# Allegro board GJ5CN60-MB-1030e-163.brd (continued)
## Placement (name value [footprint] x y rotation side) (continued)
R424  -  [M-R0402]  68.15 170.89 0 top
R425  -  [M-R0402]  64.85 170.89 180 top
R426  -  [M-R0402]  72.47 170.01 180 top
R427  -  [M-R0402]  63.07 170.89 0 top
R428  -  [M-R0402]  65.73 170.01 0 top
R429  -  [M-R0402]  70.69 170.01 0 top
R430  -  [M-R0402]  58.5 163.4 180 top
R431  -  [M-R0402]  102.44 23.83 0 top
R432  -  [M-R0402]  117.93 130 180 top
R433  -  [M-R0402]  117.93 132.29 180 top
R434  -  [M-R0402]  95.2 47.2 90 top
R435  -  [M-R0402]  92.91 20.78 90 top
R436  -  [M-R0402]  86.31 76.66 90 top
R437  -  [M-R0402]  97.23 76.66 90 top
R438  -  [M-R0402]  93.55 74.63 90 top
R439  -  [M-R0402]  92.66 74.6 270 top
R440  -  [M-R0402]  96.34 74.63 270 top
R441  -  [M-R0402]  88.47 76.66 90 top
R442  -  [M-R0402]  113.36 12.4 90 top
R443  -  [M-R0402]  95.45 7.57 180 top
R444  -  [M-R0402]  71.14 172.93 90 top
R460  -  [M-R0402]  154.63 12.14 270 top
R463  -  [M-R0402]  72.03 172.93 90 top
R472  -  [M-R0402]  153.36 12.14 270 top
R475  -  [M-R0402]  145.52 53.34 180 bottom
R477  -  [M-R0402]  66.12 172.88 90 top
R482  -  [M-R0402]  151.18 50.14 0 bottom
R483  -  [M-R0402]  145.52 50.68 180 bottom
R484  -  [M-R0402]  109.8 6.05 270 bottom
R485  -  [M-R0402]  108.91 6.05 270 bottom
R486  -  [M-R0402]  149.86 53.6 0 bottom
R487  -  [M-R0402]  126.06 6.56 180 top
R488  -  [M-R0402]  126.19 8.21 180 top
R489  -  [M-R0402]  55.19 158.7 180 top
R492  -  [M-R0402]  145.52 51.57 180 bottom
R493  -  [M-R0402]  56.72 163.4 180 top
R494  -  [M-R0402]  55.07 163.91 270 top
R495  -  [M-R0402]  54.18 163.91 90 top
R496  -  [M-R0402]  67 172.88 90 top
R497  -  [M-R0402]  68.66 172.93 90 top
R498  -  [M-R0402]  69.54 172.93 90 top
R499  -  [M-R0402]  63.58 172.93 90 top
R500  -  [M-R0402]  64.46 172.93 90 top
R501  -  [M-R0402]  151.18 51.92 0 bottom
R502  -  [M-R0402]  71.2 175.72 90 top
R504  -  [M-R0402]  72.08 175.72 90 top
R505  -  [M-R0402]  188.29 152.99 180 top
R506  -  [M-R0603]  62.84 160.28 0 top
R507  -  [M-R0402]  66.12 175.72 90 top
R508  -  [M-R0805]  183.69 77.47 0 bottom
R509  -  [M-R0402]  71.5 164.34 90 top
R510  -  [M-R0603]  186.13 72.04 90 bottom
R511  -  [M-R0402]  190.07 143.34 180 top
R512  -  [M-R0402]  190.07 142.45 0 top
R513  -  [M-R0402]  181.81 154.89 180 top
R514  -  [M-R0402]  190.45 149.81 90 top
R515  -  [M-R0402]  191.34 149.81 270 top
R516  -  [M-R0402]  67 175.72 90 top
R517  -  [M-R0402]  69.54 175.72 90 top
R518  -  [M-R0402]  68.66 175.72 90 top
R519  -  [M-R0402]  64.46 175.72 90 top
R521  -  [M-R0402]  190.07 141.56 0 top
R522  -  [M-R0402]  178.89 147.02 0 top
R523  -  [M-R0402]  178.89 147.91 0 top
R524  -  [M-R0402]  178.89 148.8 0 top
R525  -  [M-R0402]  178.89 149.81 0 top
R526  -  [M-R0402]  178.89 150.96 0 top
R527  -  [M-R0402]  178.89 151.84 0 top
R528  -  [M-R0402]  77.67 155.71 0 bottom
R529  -  [M-R0402]  185.88 139.02 90 top
R530  -  [M-R0402]  186.89 139.02 90 top
R531  -  [M-R0402]  187.91 139.02 90 top
R532  -  [M-R0402]  183.69 154 0 top
R533  -  [M-R0402]  183.69 154.89 0 top
R534  -  [M-R0402]  182.7 140.92 180 top
R535  -  [M-R0402]  182.7 140.03 0 top
R536  -  [M-R0402]  184.1 141.13 90 top
R537  -  [M-R0402]  63.58 175.72 90 top
R538  -  [M-R0402]  184.99 141.18 90 top
R539  -  [M-R0402]  180.54 141.3 90 top
R542  -  [M-R0402]  77.67 154.82 0 bottom
R544  -  [M-R0402]  58.62 175.21 0 top
R547  -  [M-R0402]  181.43 141.3 90 top
R548  -  [M-R0402]  178.38 141.81 90 top
R549  -  [M-R0402]  176.73 141.81 270 top
R550  -  [M-R0402]  178.89 144.1 0 top
R551  -  [M-R0402]  178.89 143.21 0 top
R552  -  [M-R0603]  14.05 84.92 90 top
R553  -  [M-R0402]  178.51 145.49 90 top
R554  -  [M-R0402]  177.62 145.49 270 top
R557  -  [M-R0402]  166.45 13.8 90 bottom
R558  -  [M-R0402]  178.89 154.51 0 top
R559  -  [M-R0402]  178.89 153.62 180 top
R560  -  [M-R0402]  185.88 152.99 180 top
R566  -  [M-R0402]  126.03 158.78 180 top
R567  -  [M-R0402]  134.52 158.93 180 top
R568  -  [M-R0402]  141.63 158.3 180 top
R569  -  [M-R0402]  117.85 158.73 180 top
R570  -  [M-R0402]  152.09 152.99 180 top
R571  -  [M-R0402]  160.98 153.17 180 top
R573  -  [M-R0402]  126.06 157.56 180 top
R574  -  [M-R0402]  133.93 157.58 90 top
R575  -  [M-R0402]  141.65 157.38 180 top
R576  -  [M-R0402]  117.85 157.43 180 top
R577  -  [M-R0402]  151.66 152.12 180 top
R578  -  [M-R0402]  160.96 152.1 180 top
R579  -  [M-R0603]  132.28 153.77 0 top
R580  -  [M-R0603]  139.78 153.55 0 top
R581  -  [M-R0603]  148.11 153.65 0 top
R582  -  [M-R0603]  124.69 153.93 0 top
R583  -  [M-R0603]  159.18 148.67 0 top
R584  -  [M-R0603]  168.6 148.03 90 top
R585  -  [M-R0402]  177.75 164.54 270 top
R586  -  [M-R0402]  19.4 156.29 0 bottom
R599  -  [M-R0402]  128.17 171.02 270 top
R600  -  [M-R0402]  129.06 171.02 270 top
R605  -  [M-R0402]  131.44 171.02 270 top
R606  -  [M-R0402]  130.55 171.02 270 top
R607  -  [M-R0402]  133.6 171 270 top
R608  -  [M-R0402]  132.71 171 270 top
R623  -  [M-R0402]  116.41 168.61 0 top
R624  -  [M-R0402]  82.23 173.06 0 top
R625  -  [M-R0402]  89.6 173.06 0 top
R626  -  [M-R0402]  86.43 173.06 0 top
R627  -  [M-R0402]  84.01 173.06 0 top
R632  -  [M-R0402]  152.65 178.23 90 bottom
R653  -  [M-R0402]  174.7 163.78 270 top
R661  -  [M-R0402]  112.98 5.54 90 bottom
R662  -  [M-R0402]  111.2 5.54 270 bottom
R664  -  [M-R0603]  100.91 4.65 0 bottom
R674  -  [M-R0402]  53.54 170.26 0 top
R687  -  [M-R0402]  122.5 168.99 90 bottom
R688  -  [M-R0402]  117.93 166.96 90 bottom
R691  -  [M-R0402]  192.61 147.15 180 top
R750  -  [M-R0402]  192.61 146.13 180 top
R756  -  [M-R0402]  106.12 84.92 0 top
R764  -  [M-R0402]  105.87 63.45 270 top
R765  -  [M-R0402]  106.12 84.03 0 top
R780  -  [M-R0402]  190.07 145.24 0 top
R785  -  [M-R0402]  192.61 145.24 180 top
R787  -  [M-R0402]  100.53 77.8 0 top
R790  -  [M-R0402]  100.53 76.91 180 top
R791  -  [M-R0402]  100.53 79.58 0 top
R792  -  [M-R0402]  100.53 81.36 0 top
R793  -  [M-R0402]  151.76 178.23 90 bottom
R794  -  [M-R0402]  190.07 148.03 180 top
R795  -  [M-R0402]  13.16 64.09 180 top
R803  -  [M-R0402]  181.81 154 180 top
R812  -  [M-R0402]  1.85 103.58 270 top
R815  -  [M-R0402]  100.53 78.69 180 top
R816  -  [M-R0402]  95.45 76.66 90 top
R817  -  [M-R0402]  95.45 74.63 90 top
R818  -  [M-R0402]  100.53 76.15 0 top
R819  -  [M-R0402]  100.53 80.47 180 top
R820  -  [M-R0402]  97.74 72.34 0 top
R821  -  [M-R0402]  99.14 76.66 90 top
R822  -  [M-R0402]  98.12 74.63 270 top
R823  -  [M-R0402]  100.53 74.25 0 top
R824  -  [M-R0402]  98.12 76.66 90 top
R825  -  [M-R0402]  97.74 71.45 180 top
R828  -  [M-R0402]  93.04 61.17 180 top
R832  -  [M-R0402]  95.07 59.64 0 top
R834  -  [M-R0402]  93.04 60.28 0 top
R835  -  [M-R0402]  3.89 104.22 270 top
R836  -  [M-R0402]  9.47 106.89 90 top
R837  -  [M-R0603]  10.36 97.74 270 top
R838  -  [M-R0603]  10.49 101.04 180 top
R842  -  [M-R0603]  183.64 103.94 90 top
R845  -  [M-R0402]  92.53 76.66 90 top
R849  -  [M-R0402]  82.63 57.86 0 top
R850  -  [M-R0402]  4.01 113.62 180 top
R854  -  [M-R0402]  187.55 105.24 0 top
R860  -  [M-R0402]  97.74 73.23 0 top
R861  -  [M-R0402]  97.23 74.63 270 top
R867  -  [M-R0402]  2.11 113.62 180 top
R869  -  [M-R0402]  6.96 107.52 180 top
R879  -  [M-R0402]  176.61 11.26 90 top
R880  -  [M-R0402]  190.19 8.46 0 top
R881  -  [M-R0402]  178.76 17.86 180 top
R882  -  [M-R0402]  153.49 9.73 90 top
R883  -  [M-R0402]  154.51 9.73 90 top
R884  -  [M-R0402]  150.44 11.64 90 top
R885  -  [M-R0402]  151.46 11.64 90 top
R886  -  [M-R0402]  188.16 8.46 0 top
R887  -  [M-R0402]  73.86 121.62 180 bottom
R888  -  [M-R0402]  83.13 121.49 0 bottom
R889  -  [M-R0402]  175.98 15.35 180 top
R890  -  [M-R0402]  63.7 141.56 270 bottom
R892  -  [M-R0402]  54.81 103.97 0 bottom
R893  -  [M-R0402]  94.06 140.41 180 bottom
R894  -  [M-R0402]  63.7 136.1 270 bottom
R895  -  [M-R0402]  94.06 138.13 180 bottom
R896  -  [M-R0402]  53.67 68.28 180 top
R897  -  [M-R0402]  47.7 69.29 270 top
R898  -  [M-R0402]  35.89 106.76 0 bottom
R899  -  [M-R0402]  47.95 65.74 90 top
R900  -  [M-R0402]  47.7 67.52 90 top
R901  -  [M-R0402]  53.67 69.42 0 top
R902  -  [M-R0402]  94.44 29.04 90 top
R903  -  [M-R0402]  38.56 106.76 0 bottom
R904  -  [M-R0402]  62.81 142.07 270 bottom
R905  -  [M-R0402]  79.7 54.44 0 top
R906  -  [M-R0402]  62.05 137.11 270 bottom
R907  -  [M-R0402]  55.96 115.52 0 bottom
R909  -  [M-R0805]  100.91 6.56 0 bottom
R911  -  [M-R0402]  60.91 162 90 top
R912  -  [M-R0402]  68.22 161.75 270 top
R913  -  [M-R0402]  56.01 86.44 0 bottom
R914  -  [M-R0402]  53.8 101.17 0 top
R915  -  [M-R0402]  37.41 72.34 180 bottom
R916  -  [M-R0402]  37.41 104.6 180 bottom
R917  -  [M-R0402]  39.19 72.34 180 bottom
R918  -  [M-R0603]  23.95 74.37 270 bottom
R919  -  [M-R0402]  39.19 104.6 180 bottom
R920  -  [M-R0402]  76.4 77.04 0 top
R921  -  [M-R0402]  66.37 75.39 90 top
R922  -  [M-R0402]  24.21 68.15 180 bottom
R923  -  [M-R0402]  26.11 68.53 180 bottom
R924  -  [M-R0402]  92.66 43.51 0 top
R925  -  [M-R0603]  22.55 74.37 270 bottom
R926  -  [M-R0402]  17.98 102.44 0 top
R927  -  [M-R0402]  12.27 72.6 0 top
R928  -  [M-R0402]  19.18 66.3 90 bottom
R930  -  [M-R0402]  20.27 66.3 90 bottom
R931  -  [M-R0402]  90.25 46.31 90 top
R933  -  [M-R0402]  13.41 112.22 90 top
R934  -  [M-R0805]  89.61 67.77 180 top
R935  -  [M-R0402]  17.09 111.08 90 top
R936  -  [M-R0402]  17.09 109.05 90 top
R937  -  [M-R0402]  102.06 162.77 90 top
R938  -  [M-R0402]  26.11 67.67 180 bottom
R939  -  [M-R0402]  24.21 70.03 0 bottom
R940  -  [M-R0402]  106.37 8.33 90 top
R941  -  [M-R0402]  104.98 161.37 90 top
R942  -  [M-R0402]  63.88 62.56 270 bottom
R943  -  [M-R0402]  14.3 116.41 0 top
R944  -  [M-R0402]  26.57 70.01 270 bottom
R945  -  [M-R0402]  14.3 115.52 180 top
R946  -  [M-R0402]  99.74 111.64 270 top
R947  -  [M-R0402]  16.33 68.28 0 bottom
R948  -  [M-R0402]  14.68 107.27 270 top
R949  -  [M-R0402]  24.21 69.04 180 bottom
R950  -  [M-R0402]  22.81 119.33 0 top
R951  -  [M-R0402]  190.07 147.15 0 top
R952  -  [M-R0402]  21.64 108.79 180 top
R953  -  [M-R0402]  190.07 146.13 0 top
R954  -  [M-R0402]  19.38 72.09 270 top
R955  -  [M-R0402]  24.43 111.08 90 top
R956  -  [M-R0402]  25.68 70.01 270 bottom
R957  -  [M-R0402]  24.08 108.66 180 top
R958  -  [M-R0402]  16.33 71.83 180 bottom
R959  -  [M-R0402]  13.92 70.56 270 bottom
R960  -  [M-R0402]  22.05 67.64 0 bottom
R961  -  [M-R0402]  16.2 73.74 0 bottom
R962  -  [M-R0402]  22.1 66.78 180 bottom
R963  -  [M-R0402]  76.53 47.7 90 top
R964  -  [M-R0402]  25.98 71.83 0 bottom
R965  -  [M-R0402]  23.72 66.73 270 bottom
R966  -  [M-R0402]  77.67 55.32 90 top
R967  -  [M-R0402]  18.49 67.64 180 bottom
R968  -  [M-R0402]  16.2 67.39 180 bottom
R969  -  [M-R0402]  16.2 74.63 0 bottom
R970  -  [M-R0603]  21.06 120.48 90 top
R971  -  [M-R0402]  18.87 111.08 90 top
R972  -  [M-R0402]  23.32 115.9 180 top
R973  -  [M-R0402]  16.33 73.61 0 top
R974  -  [M-R0402]  14.3 112.22 90 top
R975  -  [M-R0402]  15.19 112.22 90 top
R976  -  [M-R0402]  15.7 110.7 180 top
R977  -  [M-R0402]  73.99 47.7 270 top
R978  -  [M-R0402]  73.61 51.39 270 top
R979  -  [M-R0402]  23.32 114.89 180 top
R980  -  [M-R0402]  12.14 81.11 180 top
R981  -  [M-R0402]  23.32 131.14 180 top
R982  -  [M-R0402]  23.44 146.51 180 top
R983  -  [M-R0402]  23.32 158.58 180 top
R984  -  [M-R0402]  23.32 114 180 top
R985  -  [M-R0402]  23.29 113.13 180 top
R986  -  [M-R0402]  68.32 159.85 90 top
R987  -  [M-R0402]  19.38 108.79 270 top
R988  -  [M-R0402]  14.17 72.72 0 bottom
R989  -  [M-R0402]  79.83 157.31 90 bottom
R990  -  [M-R0402]  25.22 114 180 top
R991  -  [M-R0402]  25.22 114.89 180 top
R992  -  [M-R0402]  22.68 111.08 90 top
R993  -  [M-R0402]  18.24 70.69 90 top
R994  -  [M-R0402]  21.79 111.08 90 top
R995  -  [M-R0402]  25.22 112.8 180 top
R996  -  [M-R0402]  20.9 111.08 90 top
R997  -  [M-R0402]  16.33 70.06 180 bottom
R998  -  [M-R0402]  14.68 109.05 90 top
R999  -  [M-R0402]  16.33 70.95 180 bottom
R1000  -  [M-R0402]  107.26 8.33 90 top
R1001  -  [M-R0805]  79.2 61.8 90 top
R1002  -  [M-R0402]  20.22 108.82 270 top
R1007  -  [M-R0402]  79.83 48.59 270 top
R1010  -  [M-R0402]  181.28 74.93 270 bottom
R1014  -  [M-R0402]  183.64 68.33 0 bottom
R1022  -  [M-R0402]  68.4 155.4 90 bottom
R1054  -  [M-R0603]  21.03 147.4 90 top
R1060  -  [M-R0402]  19.13 131.4 180 top
R1061  -  [M-R0402]  19.76 137.62 180 top
R1064  -  [M-R0603]  21.03 149.94 180 top
R1065  -  [M-R0603]  20.27 122.51 180 top
R1066  -  [M-R0402]  23.19 150.07 0 top
R1083  VALUE  [TOPSHORT-R0201]  11.38 59.26 270 bottom
R1084  VALUE  [TOPSHORT-R0201]  3.89 117.05 0 top
R1085  VALUE  [TOPSHORT-R0201]  5.66 59.13 270 top
R1091  VALUE  [TOPSHORT-R0201]  10.62 59.26 270 bottom
R1092  VALUE  [TOPSHORT-R0201]  3.89 117.94 0 top
R1093  VALUE  [TOPSHORT-R0201]  5.03 59.13 270 top
R1125  -  [M-R0402]  4.77 108.41 180 top
R1126  -  [M-R0402]  5.13 109.86 90 top
R1397  -  [M-R0402]  84.91 45.8 0 top
R1398  -  [M-R0402]  95.96 161.12 0 top
R1794  -  [M-R0402]  24.08 107.01 90 top
R1795  -  [M-R0402]  11.76 105.11 180 top
R1907  -  [M-R0402]  89.99 51.39 0 top
R1908  -  [M-R0402]  94.82 45.67 180 top
R1912  -  [M-R0402]  98.5 53.42 180 top
R1920  -  [M-R0402]  95.33 44.28 270 top
R1921  -  [M-R0402]  93.55 44.66 0 top
R1925  -  [M-R0402]  98.5 51.51 180 top
R1929  -  [M-R0402]  21.28 102.44 0 top
R1932  -  [M-R0402]  14.3 113.74 0 top
R1934  -  [M-R0603]  12.65 99.39 270 top
R1936  -  [M-R0402]  94.18 47.2 270 top
R2665  -  [M-R0402]  169.62 12.91 90 top
R2667  -  [M-R0402]  173.94 9.6 270 top
R2685  -  [M-R0402]  79.2 138.76 180 bottom
R2686  -  [M-R0402]  81.48 139.02 0 bottom
R2691  -  [M-R0402]  78.31 140.16 90 top
R2692  -  [M-R0402]  79.32 140.16 270 top
R2693  -  [M-R0402]  80.21 140.16 90 top
R2712  -  [M-R0402]  35.51 122.25 0 top
R2713  -  [M-R0402]  38.43 122 0 top
R2714  -  [M-R0402]  36.14 87.46 0 top
R2715  -  [M-R0402]  37.03 120.73 180 bottom
R2716  -  [M-R0402]  36.91 121.87 270 top
R2717  -  [M-R0402]  38.05 87.46 0 top
R2718  -  [M-R0402]  38.43 84.28 0 bottom
R2719  -  [M-R0402]  36.14 88.34 180 top
R2729  -  [M-R0402]  96.97 109.71 0 bottom
R2731  -  [M-R0402]  46.3 138.89 0 bottom
R2732  -  [M-R0402]  37.03 90 180 bottom
R2733  -  [M-R0402]  79.2 135.97 180 bottom
R2734  -  [M-R0402]  81.48 136.35 0 bottom
R2735  -  [M-R0402]  79.2 136.86 180 bottom
R2736  -  [M-R0402]  81.48 137.24 0 bottom
R2737  -  [M-R0402]  40.97 122.13 270 bottom
R2738  -  [M-R0402]  40.08 122.13 270 bottom
R2739  -  [M-R0402]  46.3 136.22 0 bottom
R2740  -  [M-R0402]  46.3 137.11 0 bottom
R2741  -  [M-R0402]  40.99 87.18 270 bottom
R2742  -  [M-R0402]  40 87.18 270 bottom
R2745  -  [M-R0402]  39.95 89.49 90 bottom
R2746  -  [M-R0402]  40.84 89.49 90 bottom
R2751  -  [M-R0402]  2.36 108.41 0 top
R2755  -  [M-R0402]  4.24 109.83 270 top
R2758  -  [M-R0402]  69.92 109.43 270 bottom
R2759  -  [M-R0402]  68.27 121.87 90 bottom
R2760  -  [M-R0402]  69.16 121.87 90 bottom
R2771  -  [M-R0402]  95.71 84.79 270 bottom
R2773  -  [M-R0402]  2.36 109.3 180 top
R2781  -  [M-R0402]  94.51 76.66 270 top
R2798  -  [M-R0402]  98.5 59.95 270 top
R2799  -  [M-R0402]  102.44 94.57 0 top
R2800  -  [M-R0402]  102.44 93.68 0 top
R2801  -  [M-R0402]  93.55 76.66 270 top
R2803  -  [M-R0402]  87.45 76.66 90 top
R2806  -  [M-R0402]  91.01 84.66 90 bottom
R2808  -  [M-R0402]  91.67 74.6 270 top
R2809  -  [M-R0402]  90.5 74.63 270 top
R2810  -  [M-R0402]  94.56 74.63 90 top
R2811  -  [M-R0402]  90.5 76.66 90 top
R2812  -  [M-R0402]  88.34 74.76 90 top
R2813  -  [M-R0402]  89.61 74.63 270 top
R2814  -  [M-R0402]  96.34 76.66 90 top
R2815  -  [M-R0402]  91.64 76.66 90 top
R2836  -  [M-R0402]  89.36 76.66 270 top
R2848  -  [M-R0402]  92.4 70.95 180 top
R2849  -  [M-R0402]  92.4 71.83 180 top
R2850  -  [M-R0402]  93.8 67.01 90 top
R2865  -  [M-R0402]  103.58 72.98 0 top
R2875  -  [M-R0402]  100.53 73.36 180 top
R2876  -  [M-R0402]  100.53 72.47 0 top
R2877  -  [M-R0402]  105.23 82.12 180 top
R2878  -  [M-R0402]  91.77 86.06 0 bottom
R2879  -  [M-R0402]  20.65 72.09 270 top
R2880  -  [M-R0402]  16.33 119.21 180 top
R2881  -  [M-R0402]  105.36 72.98 0 top
R2921  -  [M-R0402]  94.82 70.95 0 top
R2924  -  [M-R0402]  92.4 72.72 180 top
R2925  -  [M-R0402]  92.28 67.01 90 top
R2938  -  [M-R0402]  87.58 72.47 270 top
R2939  -  [M-R0402]  100.15 112.98 0 top
R2940  -  [M-R0402]  20.65 106.89 270 top
R2941  -  [M-R0402]  13.03 70.56 90 bottom
R2942  -  [M-R0402]  21.67 106.89 270 top
R2949  -  [M-R0402]  87.45 74.76 270 top
R3036  -  [M-R0402]  72.85 162.39 270 top
R3129  -  [M-R0402]  167.97 130 180 top
R3197  -  [M-R0402]  192.35 119.59 180 top
R3198  -  [M-R0402]  190.45 116.28 180 top
R3201  -  [M-R0402]  187.53 104.35 0 top
R3202  -  [M-R0402]  188.72 102.92 270 top
R3204  -  [M-R0402]  108.53 73.49 90 top
R3240  -  [M-R0402]  103.2 5.92 90 bottom
R3247  -  [M-R0402]  93.04 7.57 180 top
R3290  -  [M-R0402]  156.41 25.23 0 top
R3295  -  [M-R0402]  63.58 37.67 270 top
R3298  -  [M-R0402]  62.69 37.67 270 top
R3299  -  [M-R0402]  72.34 40.08 0 top
R3305  -  [M-R0402]  69.54 37.67 90 top
R3306  -  [M-R0402]  66.24 37.67 90 top
R3307  -  [M-R0402]  61.42 45.93 180 top
R3308  -  [M-R0402]  68.66 37.67 270 top
R3309  -  [M-R0402]  72.47 41.23 180 top
R3310  -  [M-R0402]  69.93 44.28 0 top
R3311  -  [M-R1206]  19.38 42.62 0 top
R3312  -  [M-R0603]  50.62 56.98 180 top
R3313  -  [M-R0402]  44.02 39.58 90 bottom
R3314  -  [M-R0402]  37.79 41.48 270 bottom
R3315  -  [M-R0402]  39.95 41.48 270 bottom
R3316  -  [M-R0402]  40.59 36.78 90 top
R3318  -  [M-R0402]  63.58 45.93 180 top
R3319  -  [M-R0402]  65.35 37.67 90 top
R3320  -  [M-R0402]  69.93 42.24 0 top
R3321  -  [M-R0603]  67.39 35.26 90 top
R3322  -  [M-R0402]  64.46 37.67 90 top
R3323  -  [M-R0402]  72.47 43.39 180 top
R3324  -  [M-R0402]  43.13 41.48 270 bottom
R3325  -  [M-R0402]  73.48 35.26 90 top
R3326  -  [M-R0402]  45.92 156.67 0 bottom
R3327  -  [M-R0402]  64.97 46.18 90 top
R3328  -  [M-R0402]  60.15 44.53 270 top
R3329  -  [M-R0402]  59.26 44.53 90 top
R3330  -  [M-R0402]  60.65 41.48 180 top
R3331  -  [M-R0402]  61.67 38.81 90 top
R3332  -  [M-R0402]  69.04 46.31 90 top
R3333  -  [M-R0402]  28.9 38.05 270 top
R3334  -  [M-R0402]  69.93 43.39 180 top
R3335  -  [M-R0402]  68.15 46.31 90 top
R3336  -  [M-R0402]  65.86 46.18 90 top
R3361  -  [M-R0402]  91.52 42.57 180 top
R3365  -  [M-R0402]  84.66 47.32 90 top
R3366  -  [M-R0402]  97.13 162.77 90 top
R3367  -  [M-R0402]  84.66 49.23 90 top
R3368  -  [M-R0402]  87.32 49.23 270 top
R3369  -  [M-R0402]  98.86 163.27 180 top
R3370  -  [M-R0402]  103.83 162.77 270 top
R3372  -  [M-R0402]  111.33 124.62 0 bottom
R3375  -  [M-R0402]  95.33 162.77 270 top
R3376  -  [M-R0402]  111.33 126.65 0 bottom
R3377  -  [M-R0402]  111.33 127.54 0 bottom
R3379  -  [M-R0402]  102.77 159.13 180 top
R3381  -  [M-R0402]  187.91 98.38 180 top
R3382  -  [M-R0402]  193.8 96.22 180 top
R3385  -  [M-R0402]  86.44 47.32 270 top
R3395  -  [M-R0402]  85.55 49.23 270 top
R3402  -  [M-R0402]  86.44 49.23 270 top
R3494  -  [M-R0402]  101.17 162.77 90 top
R3512  -  [M-R0402]  167.33 11 270 top
R3514  -  [M-R0402]  166.45 11 270 top
R3515  -  [M-R0402]  146.25 5.67 90 bottom
R3516  -  [M-R0603]  100.91 3.25 0 bottom
R3517  -  [M-R0402]  143.84 5.54 270 bottom
R3518  -  [M-R0402]  159.21 3.76 90 bottom
R3519  -  [M-R0603]  100.91 1.86 0 bottom
R3520  -  [M-R0402]  154.76 4.91 270 bottom
R3521  -  [M-R0402]  105.49 8.33 90 top
R3523  -  [M-R0402]  107.14 6.05 90 bottom
R3536  -  [M-R0402]  82.63 59.77 0 top
R3537  -  [M-R0402]  9.85 105.11 180 top
R3539  -  [M-R0402]  102.74 60.12 90 top
R3540  -  [M-R0402]  95.07 58.75 0 top
R3541  -  [M-R0402]  16.15 109.05 90 top
R3585  -  [M-R0402]  165.05 8.59 270 top
R3624  -  [M-R0402]  17.63 156.29 180 bottom
R3625  -  [M-R0402]  29.16 161.5 180 top
R3626  -  [M-R0402]  11.1 70.56 270 bottom
R3627  -  [M-R0402]  18.24 58.37 90 bottom
R3628  -  [M-R0402]  17.22 58.37 90 bottom
R3654  -  [M-R0402]  117.93 168.74 90 bottom
R3692  -  [M-R0402]  91.52 155.53 0 bottom
R3693  -  [M-R0402]  86.82 157.94 90 bottom
R3694  -  [M-R0402]  112.47 170.77 270 top
R3695  -  [M-R0402]  111.45 170.77 270 top
R3697  -  [M-R0402]  114.45 170.77 270 top
R3698  -  [M-R0402]  113.54 170.77 270 top
R3699  -  [M-R0402]  109.04 170.77 270 top
R3700  -  [M-R0402]  110.06 170.77 270 top
R3702  -  [M-R0402]  166.45 8.59 90 top
R3710  -  [M-R0402]  11.76 47.07 0 bottom
R3711  -  [M-R0402]  11.76 47.96 0 bottom
R3716  -  [M-R0402]  104.6 8.33 270 top
R3721  -  [M-R0402]  11.68 61.83 0 bottom
R3722  -  [M-R0402]  24.18 71.81 0 bottom
R3723  -  [M-R0402]  174.95 155.02 90 top
R3724  -  [M-R0402]  181.3 165.05 270 top
R3820  -  [M-R0402]  99.77 162.89 180 bottom
R3821  -  [M-R0402]  99.77 162 0 bottom
R3822  -  [M-R0402]  184.76 114.74 270 top
RCH1  -  [M-R1206]  49.61 38.05 90 top
RCH2  -  [M-R1206]  47.19 38.05 90 top
RT10  -  [M-R0603]  143.97 15.19 0 bottom
S1  -  [SCON2S]  28.51 172.05 90 bottom
S4  -  [SCON2S]  164.53 172.3 270 bottom
S5  -  [SCON2S]  79.37 38.63 180 bottom
S6  -  [SCON2S]  80.67 38.63 180 bottom
S7  -  [SCON2S]  76.88 38.61 180 bottom
S8  -  [SCON2S]  78.05 38.63 180 bottom
S10  *  [SCON2S]  64.79 179.53 0 bottom
S11  *  [SCON2S]  63.8 179.53 0 bottom
S12  *  [SCON2S]  69.29 180.04 180 bottom
S13  *  [SCON2S]  68.32 180.04 180 bottom
S14  -  [SCON2S]  69.29 157.81 90 bottom
S15  -  [SCON2S]  74.62 157.56 90 bottom
S16  -  [SCON2S]  75.51 157.56 270 bottom
S17  -  [SCON2S]  184.1 162.39 270 top
S18  *  [SCON2S]  66.09 155.86 90 bottom
S19  *  [SCON2S]  67.79 179.53 0 bottom
S20  *  [SCON2S]  66.8 179.56 0 bottom
S21  *  [SCON2S]  66.24 181.11 0 bottom
S22  *  [SCON2S]  65.35 181.11 0 bottom
S23  *  [SCON2S]  55.19 172.16 180 top
S25  -  [SCON2S]  126.35 176.39 90 bottom
S26  -  [SCON2S]  130.88 174.94 270 bottom
S27  -  [SCON2S]  129.89 176.41 270 bottom
S28  -  [SCON2S]  132.83 174.86 270 bottom
S29  -  [SCON2S]  133.87 176.39 270 bottom
S30  -  [SCON2S]  135.9 176.41 270 bottom
S106  -  [SCON2S]  40.97 48.72 180 top
S107  -  [SCON2S]  42.49 48.72 180 top
S108  -  [SCON2S]  39.45 48.72 180 top
S109  -  [SCON2S]  44.02 48.72 180 top
S110  -  [SCON2S]  15.37 162.92 90 bottom
S111  -  [SCON2S]  181.86 164.37 270 bottom
S112  -  [SCON2S]  109.8 176.48 270 bottom
S113  -  [SCON2S]  115.77 176.33 270 bottom
S114  -  [SCON2S]  112.24 176.56 90 bottom
S115  -  [SCON2S]  106.25 176.48 90 bottom
S116  -  [SCON2S]  111.56 175.67 45 bottom
S117  -  [SCON2S]  110.44 175.72 315 bottom
SW1  Value*  [SWITCH_T-V_SFNQGMP21E8T_FH]  27.4 169.1 0 bottom
SW2  Value*  [SWITCH_T-V_SFNQGMP21E8T_FH]  182.99 161.43 180 bottom
SW3  Value*  [SWITCH_T-V_SFNQGMP21E8T_FH]  14.23 161.43 180 bottom
SW5  -  [M-SOT23-3L]  121.08 172.95 180 bottom
SW6  VALUE  [SWITCH_T_V_ML4L12XQR_DIP]  165.95 170.16 180 bottom
TP1  -  [TP20]  142.37 7.7 270 top
TP2  -  [TP20]  141.05 7.7 0 top
TP3  -  [TP20]  69.16 114.76 180 bottom
TP4  -  [TP20]  9.22 72.85 0 top
TP5  -  [TP20]  3.12 70.31 0 top
TP6  -  [TP20]  3.5 65.48 0 top
TP7  -  [TP20]  149.48 111.54 180 bottom
TP9  -  [TP20]  166.45 130 0 top
TP10  -  [TP20]  122.76 12.02 0 top
TP11  -  [TP20]  166.06 124.67 0 top
TP13  -  [TP20]  119.71 103.84 0 top
TP14  -  [TP20]  147.66 111.46 180 bottom
TP15  -  [TP20]  166.32 128.22 0 top
TP16  -  [TP20]  159.43 125.2 180 bottom
TP18  -  [TP20]  122.25 14.43 180 bottom
TP19  -  [TP20]  130 18.62 180 bottom
TP20  -  [TP20]  99.59 95.99 0 top
TP21  -  [TP20]  101.04 88.85 0 top
TP23  -  [TP20]  99.8 94.49 0 top
TP24  -  [TP20]  123.62 23.14 180 bottom
TP25  -  [TP20]  124.66 20.78 180 bottom
TP26  -  [TP20]  103.58 24.84 0 top
TP27  -  [TP20]  125.17 21.67 180 bottom
TP28  -  [TP20]  122.12 12.27 180 bottom
TP29  -  [TP20]  125.45 10.57 0 top
TP30  -  [TP20]  125.04 14.81 180 bottom
TP31  -  [TP20]  119.4 12.8 0 top
TP32  -  [TP20]  100.86 95.33 0 top
TP33  -  [TP20]  125.42 11.76 0 top
TP34  -  [TP20]  100.84 96.88 0 top
TP35  -  [TP20]  102.36 95.35 0 top
TP36  -  [TP20]  101.09 93.68 0 top
TP37  -  [TP20]  100.66 23.32 0 top
TP38  -  [TP20]  103.58 19.26 0 top
TP39  -  [TP20]  164.54 111.84 0 top
TP41  -  [TP20]  165.94 120.35 0 top
TP42  -  [TP20]  165.94 119.08 0 top
TP43  -  [TP20]  167.46 119.08 0 top
TP44  -  [TP20]  167.46 120.35 0 top
TP45  -  [TP20]  166.06 111.84 0 top
TP46  -  [TP20]  164.41 113.24 0 top
TP47  -  [TP20]  166.83 113.24 0 top
TP48  -  [TP20]  165.43 113.24 0 top
TP50  -  [TP20]  124.66 11.89 180 bottom
TP51  -  [TP20]  103.71 26.5 0 top
TP52  -  [TP20]  131.77 24.21 0 top
TP53  -  [TP20]  101.68 22.43 0 top
TP54  -  [TP20]  103.83 21.92 180 bottom
TP55  -  [TP20]  104.98 23.19 180 bottom
TP95  -  [TP20]  92.68 93.6 180 bottom
TP96  -  [TP20]  91.13 93.55 180 bottom
TP150  -  [TP20]  23.62 65.31 90 top
TP151  -  [TP20]  143.84 10.11 180 bottom
TP152  -  [TP20]  144.22 12.91 180 bottom
TP184  -  [TP20]  83.77 7.7 90 top
TP185  -  [TP20]  90.68 10.01 90 bottom
TP186  -  [TP20]  91.26 11.92 180 bottom
TP187  -  [TP20]  90.17 7.9 90 top
TP190  -  [TP20]  90.02 11.81 180 bottom
TP193  -  [TP20]  88.87 7.72 0 top
TP194  -  [TP20]  88.95 11.51 90 bottom
TP198  -  [TP20]  141.53 31.32 0 bottom
TP199  -  [TP20]  164.57 31.55 180 bottom
TP1903  -  [TP20]  98.96 50.6 270 top
U1  -  [QFN-16_4X4_D65]  6.46 68.56 0 top
U2  -  [SOT-23-5]  56.22 55.59 270 top
U3  VALUE*  [QFN48_D4-6X6]  184.48 146.76 90 top
U4  MP86901-BGLT  [TQFN21_3X4_MP86901B]  129.89 156.82 90 top
U5  -  [QFPS128-04M-60]  155.02 20.91 270 bottom
U6  MP86901-BGLT  [TQFN21_3X4_MP86901B]  137.26 156.34 90 top
U7  -  [QFN48_D4-6X6]  23.32 59.77 270 top
U8  -  [M-SOP8_150MIL]  145.62 23.83 0 top
U9  APW8715QBI-TRG  [TQFN23_0D5_4X4_APW8715AA8]  189.43 94.06 270 top
U10  MP86901-BGLT  [TQFN21_3X4_MP86901B]  145.41 156.67 90 top
U11  MP86901-BGLT  [TQFN21_3X4_MP86901B]  121.66 156.75 90 top
U12  APW8715QBI-TRG  [TQFN23_0D5_4X4_APW8715AA8]  180.3 13.7 0 top
U13  MP86901-BGLT  [TQFN21_3X4_MP86901B]  155.78 151.21 90 top
U14  -  [M-SOP8_150MIL]  22.02 140.64 90 bottom
U15  MP86901-BGLT  [TQFN21_3X4_MP86901B]  164.62 151.23 90 top
U16  -  [M-SOP8_150MIL]  191.34 163.66 0 top
U17  APW8715QBI-TRG  [TQFN23_0D5_4X4_APW8715AA8]  87.58 42.75 270 top
U18  APW8715QBI-TRG  [TQFN23_0D5_4X4_APW8715AA8]  99.26 159.08 270 top
U19  *  [WDFN10-1_0D5_2D0X2D0_3X3]  62.23 61.67 90 top
U20  -  [M-SOP8-208MIL]  135.46 24.46 0 top
U23  -  [M-SOT353]  180.54 136.22 270 top
U24  -  [M-SOT353]  99.77 160.1 90 bottom
U25  VALUE  [QFN16_3X3_NB687]  186.29 108.77 180 top
U26  -  [BGA1440_CFL_H62_5_MA_KOZ]  141.98 117.38 270 top
U27  -  [M-MSOP8]  141.3 169.75 270 top
U28  -  [BGA874_CNP_H_5_MA_KOZ]  117.55 26.37 0 top
U29  -  [M-SOT353]  83.26 155.4 270 bottom
U30  *  [WDFN10-1_0D5_2D0X2D0_3X3]  85.29 57.48 180 top
U31  -  [M-MSOP8]  120.65 169.93 270 top
U32  VAL  [WDFN8_0D5_1D0_2D0X2D0]  22.09 148.35 270 bottom
U83  -  [M-SOP8_150MIL]  104.82 77.55 180 top
U84  *  [WDFN10-1_0D5_2D0X2D0_3X3]  6.93 102.7 180 top
U97  *  [QFN28-1_0D4_2D4X2D4_4X4]  65.1 41.74 0 top
U104  -  [DFN3X2-14L]  172.67 58.5 180 bottom
U105  -  [DFN3X2-14L]  114.58 125.76 90 bottom
U106  -  [DFN3X2-14L]  170.49 15.64 270 bottom
U107  -  [DFN3X2-14L]  75.01 61.55 0 top
U721  -  [QFN20_3X3_D4]  20.01 70.44 270 bottom
U722  -  [QFN4X4-24-0-5]  19 115.78 0 top
U733  -  [M-MSOP8]  105.87 165.43 270 top
U1901  VALUE*  [QFN-32_4X4_0D4]  94.44 51.64 0 top
Y1  -  [CRYSTAL-2P_3D2X1D5_0D9]  137.49 15.83 270 top
Y2  -  [CRYSTAL-4P_3D2X2D5_0D9]  103.2 51.39 270 top
Y3  -  [CRYSTAL-4P_3D2X2D5_0D9]  99.77 29.49 90 bottom
Y10  -  [CRYSTAL-4P_3D2X2D5_0D9]  101.93 84.53 90 top

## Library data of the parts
AB1 AB3-AB5 AR5 AR6 AR8 AR9 AR11-AR14 AR17 AR18 B27 B34 R1 R2 R4 R5 R7-R16 R19-R22 R24-R30 R32 R33 R36-R89 R91-R105 R107 R109-R114 R116-R119 R121-R128 R131-R146 R148 R149 R151 R153 R155-R158 R163-R180 R182-R188 R191-R208 R211 R215-R225 R227 R228 R235 R236 R241 R245-R260 R262 R264 R266 R269 R271 R273 R278 R281 R283-R309 R311-R317 R319-R321 R323 R325-R327 R329 R334-R343 R347-R350 R352-R358 R360-R363 R366-R371 R373 R375 R377-R379 R383-R386 R388 R389 R392-R394 R398 R403-R405 R408 R412-R420 R424-R444 R460 R463 R472 R475 R477 R482-R489 R492-R502 R504 R505 R507 R509 R511-R519 R521-R532 R534-R539 R542 R544 R548-R550 R554 R557-R560 R566-R571 R573-R578 R585 R586 R599 R600 R605-R608 R623-R627 R632 R653 R661 R662 R674 R687 R688 R691 R750 R756 R764 R765 R780 R785 R787 R790-R795 R803 R812 R815-R825 R828 R832 R834-R836 R845 R849 R850 R854 R860 R861 R867 R869 R879-R890 R892-R907 R911-R917 R919-R924 R926-R928 R930 R931 R933 R935-R969 R971-R1000 R1002 R1007 R1010 R1014 R1022 R1060 R1061 R1066 R1125 R1126 R1397 R1398 R1794 R1795 R1907 R1908 R1912 R1920 R1921 R1925 R1929 R1932 R1936 R2665 R2667 R2685 R2686 R2691-R2693 R2712-R2719 R2729 R2731-R2742 R2745 R2746 R2751 R2755 R2758-R2760 R2771 R2773 R2781 R2798-R2801 R2803 R2806 R2808-R2815 R2836 R2848-R2850 R2865 R2875-R2881 R2921 R2924 R2925 R2938-R2942 R2949 R3036 R3129 R3197 R3198 R3201 R3202 R3204 R3240 R3247 R3290 R3295 R3298 R3299 R3305-R3310 R3313-R3316 R3318-R3320 R3322-R3336 R3361 R3365-R3370 R3372 R3375-R3377 R3379 R3381 R3382 R3385 R3395 R3402 R3494 R3512 R3514 R3515 R3517 R3518 R3520 R3521 R3523 R3536 R3537 R3539-R3541 R3585 R3624-R3628 R3654 R3692-R3695 R3697-R3700 R3702 R3710 R3711 R3716 R3721-R3724 R3820-R3822 = M-R0402
AB2 AB6 AR25 B1 R3 R6 R31 R35 R189 R190 R213 R214 R226 R230 R232 R239 R242 R280 R310 R322 R372 R374 R376 R409 R422 R506 R510 R552 R579-R584 R664 R837 R838 R842 R918 R925 R970 R1054 R1064 R1065 R1934 R3312 R3321 R3516 R3519 RT10 = M-R0603
AB8 AB9 AB11 AB12 B7 B10 B12 B19 = M-B0603
AC3 AC5-AC7 AC9 C2 C4 C8 C13-C19 C21 C42 C44-C50 C52-C54 C56-C66 C68 C69 C72-C76 C78 C80 C82-C89 C93 C94 C96 C100 C101 C105 C107 C109 C113-C115 C118-C120 C126 C128-C131 C133 C134 C136-C142 C145 C147 C150 C151 C154-C158 C161-C166 C168 C172 C174 C175 C177-C180 C182 C183 C194 C195 C198 C203 C205 C207 C209 C214 C216 C219 C223-C237 C239-C250 C252-C282 C284-C300 C305 C308-C311 C320-C335 C339 C341 C345-C347 C349 C351-C355 C359-C378 C380-C401 C403-C418 C420-C422 C425-C432 C435 C436 C438 C445 C450 C452 C456 C465 C466 C469 C470 C473 C486 C492 C493 C498-C500 C522 C529 C540 C544-C546 C548 C550 C554 C556 C559 C581 C588 C592 C595 C602 C610 C615 C641 C653 C654 C656 C663 C665-C669 C673 C720 C738 C782-C785 C788 C789 C796-C809 C818 C819 C821-C834 C846-C849 C851-C855 C857-C859 C863 C864 C867 C868 C870 C872 C874-C888 C890 C893 C895 C898 C901 C904-C908 C911-C915 C917-C921 C924-C928 C931-C935 C939-C942 C947 C949 C950 C952 C955-C957 C963 C972 C973 C976-C982 C984-C987 C989-C992 C994-C997 C999 C1000 C1002 C1004-C1017 C1019-C1022 C1024-C1026 C1028 C1031 C1032 C1035 C1037 C1038 C1040-C1044 C1046 C1050 C1053-C1057 C1059-C1061 C1063-C1071 C1074-C1077 C1128 C1137 C1151-C1153 C1164 C1170 C1176 C1179-C1197 C1216-C1227 C1243 C1244 C1246 C1248 C1249 C1252 C1260-C1267 C1274 C1277 C1279 C1281-C1285 C1287 C1289-C1296 C1298-C1303 C1307 C1308 C1310-C1318 C1321-C1326 C1328-C1342 C1347 C1349 C1361 C1362 C1364 C1367 C1368 C1371 C1374 C1375 C1382-C1384 C1386-C1390 C1392-C1413 C1415-C1419 C1421 C1422 C1426 C1427 C1432 C1433 C1442-C1446 C1451 C1452 C1456-C1458 C1476-C1483 C1488-C1499 C1504-C1516 C2549-C2555 C2575 C2578 C2579 C2745-C2747 C2821 C3384 C3399 C3401 C3416-C3420 C3422-C3425 C3445 C3463-C3468 C3470 C3471 C3491 C3493 C3495 C3532 C3535-C3537 C3541 C3543 C3549-C3553 C3556-C3560 C3564 C3565 C3574 C3576 C3579-C3583 C3603 C3604 C3616 C3617 C3620-C3623 C3625-C3627 C3630 C3631 C3634 C3635 C3638 C3641 C3643-C3646 C3650 C3669 C3742 C3743 C3847 C3892 C3893 C3895 C3896 C3901-C3904 C3912 C3913 C3939-C3941 C3988 C3989 C4084 C4092 C4094 C4102 C4103 C4114 C4115 = M-C0402
AC4 AC8 C3 C5-C7 C9-C11 C22-C41 C43 C51 C55 C67 C70 C71 C77 C79 C81 C90-C92 C95 C97-C99 C102-C104 C106 C108 C110-C112 C116 C117 C121-C123 C125 C127 C132 C135 C143 C144 C146 C148 C149 C152 C153 C159 C160 C167 C169-C171 C173 C176 C181 C184-C193 C196 C197 C199-C202 C204 C206 C208 C210-C213 C215 C217 C218 C220-C222 C283 C340 C379 C402 C553 C577-C580 C582-C587 C589-C591 C593 C594 C596-C601 C603-C609 C611-C614 C616-C628 C677 C686-C690 C692-C703 C719 C816 C817 C856 C860-C862 C865 C866 C871 C889 C891 C892 C894 C896 C897 C899 C900 C902 C903 C909 C910 C916 C922 C923 C929 C930 C936-C938 C943-C946 C948 C951 C953 C954 C958-C962 C964-C971 C974 C975 C983 C988 C993 C998 C1001 C1003 C1018 C1023 C1027 C1029 C1030 C1033 C1034 C1036 C1039 C1045 C1047-C1049 C1051 C1052 C1058 C1062 C1072 C1073 C1078 C1138 C1139 C1144 C1161 C1163 C1165 C1167 C1169 C1234-C1237 C1245 C1247 C1250 C1251 C1253-C1259 C1268-C1273 C1275 C1276 C1278 C1280 C1286 C1288 C1297 C1304-C1306 C1309 C1319 C1320 C1327 C1343-C1346 C1348 C1350-C1358 C1363 C1370 C1378 C1385 C1391 C1414 C1423 C1425 C1429 C1431 C1434 C1440 C1441 C1447 C1448 C1450 C1454 C1455 C1463-C1468 C1470-C1472 C2396-C2398 C3421 C3426-C3428 C3431 C3432 C3438-C3441 C3443 C3447 C3496 C3538-C3540 C3544-C3548 C3554 C3561-C3563 C3566-C3573 C3575 C3577 C3578 C3584-C3602 C3605-C3615 C3618 C3619 C3624 C3628 C3629 C3632 C3636 C3637 C3642 C3647-C3649 C3651-C3661 C3744 C3745 C3747 C3898 C3990-C3992 C4085 C4093 = M-C0603
ACN1 = CON_WB-4H125_11255W90-NP_JCTC
B2 B15 B16 = M-B0402
B13 B20 B36 B37 = M-B0805: Tolerance: ***; User Part Number: ***
B14 B25 PS1 = FUSE-0805
B26 R508 R934 R1001 = M-R0805
C419 C423 C424 C433 = M-C0402: signal model: M-C0402_.22U-10-04R-K
C576 C630-C632 C1369 C1372 C1373 C1376 C1377 C1438 C3633 C3897 C3899 C3962 C4078 C4079 C4104-C4110 = M-C0805
C629 = M-C1808
C674 C1420 C1428 C1435 C1437 C1449 C1459 C1469 = M-C7343: User Part Number: ***; Tolerance: ***
C675 C1424 C1436 C1439 C1453 = M-C7343: Tolerance: ***; User Part Number: ***
C4117 C4121 = CAP_EEEFZ1E101P_6D3_L45
C4118-C4120 = CAP_EEEFZ1E101P_6D3_L60
CN1 = CON_S-DDR4-S80_D4ASX-260-80_ARG
CN4 = CON_WB_2H125_W-00-1025_JCTC
CN9 CN14 CNDEG1 = CON_WB_10H08_50208-010_ACES
CN11 = CON_S-DDR4-S40_D4ASX-260-40_ARG
CN12 = CON_FFC_50B05_FP225H050S10M_JXT
CN17 = CON_FFC_10R05_6712K-V10N07L_ENT
CN18 = CON_FFC_6R100_51524-00601_ACES
CN19 CN41 CN42 = CON_FFC_6R05-AFC34-S06FCA_HF
CN23 CN32 = CON_SUSB_3SR_UEA1111-R04012_FOX
CN26 = CON_HDMI-A-R_HAR01-191CN5V_HT
CN30 = CON_WB_13V150_51481-01371_ACES
CN34 = CON_RJ45_WO_130456-781_SANTA
CNDCIN1 = CON_DCIN_WO_2DC3003-002211_SIN
CNDEG2 = CON_WB_6H08_88460-0601_ACES
CNEDP1 = CON_FFC_40R05-51517_ACES
CNFAN1 CNFAN2 = CON_WB_3H125_3800K-F03N_ENT
CNHDD1 = CON_FFC_18B05_51625-01801_ACES
CNKB1 = CON_FFC_40TB05_6718K_Y40N_ENT
CNSSD1 CNSSD2 = CON_M2_M_S67_NXSM0-S67XX_ARG
CNWLAN1 = CON_M2-E-S67_AS0BC21-S48BE_FOX
CON3 = CON_SUSB-CS_UT11123-101W0_FXCN
D1 D3 D4 D10 D16 D28 D41 D51 D52 = M-SOT23
D23 D24 D26 D27 D29 D30 = M-SOD323
D37-D39 D42-D45 D59-D62 = DIODE-AZ5315-02F
ESD1-ESD3 = DFN10_0D5_2D5X1D0
G1 = BGA_2152_P070_375X375
H2 H4 = HOLEC276D118
H3 = GI_H3
H5-H7 H25 = C315D110
H8 = GI_H8
H12 = GI_H12
H13-H15 H18-H20 = HOLEC295D157
H16 = C236D158
H23 = C197D79
H24 = HOLEC197D71
JP1 JP2 = TOPOPEN_20X30
L3 L10 L11 L28 L43 = CHOKE_7D6X6D8_4
L12 L14 L15 L17 = CHOKE-7D3_8D3_5
L13 L20 L21 L35 L50 L53 = CHOKE-7D3_6D8_3
L16 L22-L27 L29 L34 L36-L38 L44 L45 L48 L51 L65-L67 = CHOKE-4P_2X1_2X1_2
L46 L49 L62 = CHOKE-4D1_4D0_2D0
L52 = CHOKE_3X3_1D7
L54 = CHOKE_3X3_1D5
LED1 = LED_19-223-R7G: User Part Number: ***; Tolerance: ***
LED2 LED4 = LED_WHITE_4_RNM_RNM: User Part Number: ***; Tolerance: ***
LT2 = GST5009
M1-M8 = M-MARK1
M41-M46 = BGA_0170_P080_140X120
PJP5 PJP11 PJP13 PJP15 PJP28 PJP34 PJP3210 = TOPSHORT_20X30
PJP9 PJP10 PJP12 PJP14 PJP16-PJP24 = TOPOPEN_20X79
PQ37 PQ40-PQ44 PQ48 PQ49 PQ52 PQ53 = PDFN5X6P_8_DUALMOS
Q1 Q5 Q12 Q19 Q27 Q30 Q37 Q42 Q48-Q50 Q54 Q55 Q57 Q59 Q62-Q64 Q66-Q71 Q78 Q86 Q101 Q105 Q106 Q123-Q126 Q129 Q136 Q137 Q139 Q146-Q148 Q155 Q157-Q163 Q183 Q188 Q190 = M-SOT23G
Q2-Q4 Q16 Q44 Q47 Q58 Q60 Q88 Q92 Q100 Q104 Q109 Q113 Q114 Q116 Q119 Q120 Q122 Q128 Q130 = SOT363
Q8-Q10 = PQFN8-PPS
Q20 Q45 Q53 = M-SOT23A: Tolerance: ***; User Part Number: ***
Q41 Q43 = PDFN-8P_B3X3_D65
Q51 Q182 = M-SOT23A: User Part Number: ***; Tolerance: ***
Q96 = M-SOT353: User Part Number: ***; Tolerance: ***
Q99 Q165 U23 U24 U29 = M-SOT353: Tolerance: ***; User Part Number: ***
R150 R181 R359 R365 R533 R547 R551 R553 = M-R0402: signal model: M-R0402_0-04
R344-R346 R387 R3311 RCH1 RCH2 = M-R1206
R351 R364 R380-R382 R390 = M-R0805: Tolerance: ***; User Part Number: ***
R909 = M-R0805: signal model: SMR0402_33-1-04
R1083-R1085 R1091-R1093 = TOPSHORT-R0201
S1 S4-S8 S10-S23 S25-S30 S106-S117 = SCON2S
SW1-SW3 = SWITCH_T-V_SFNQGMP21E8T_FH
SW5 = M-SOT23-3L: Tolerance: ***; User Part Number: ***
SW6 = SWITCH_T_V_ML4L12XQR_DIP
TP1-TP7 TP9-TP11 TP13-TP16 TP18-TP21 TP23-TP39 TP41-TP48 TP50-TP55 TP95 TP96 TP150-TP152 TP184-TP187 TP190 TP193 TP194 TP198 TP199 TP1903 = TP20
U1 = QFN-16_4X4_D65
U2 = SOT-23-5
U3 U7 = QFN48_D4-6X6
U4 U6 U10 U11 U13 U15 = TQFN21_3X4_MP86901B
U5 = QFPS128-04M-60: User Part Number: ***
U8 U14 U16 U83 = M-SOP8_150MIL
U9 U12 U17 U18 = TQFN23_0D5_4X4_APW8715AA8
U19 U30 U84 = WDFN10-1_0D5_2D0X2D0_3X3
U20 = M-SOP8-208MIL
U25 = QFN16_3X3_NB687
U26 = BGA1440_CFL_H62_5_MA_KOZ
U27 U31 U733 = M-MSOP8: User Part Number: ***
U28 = BGA874_CNP_H_5_MA_KOZ
U32 = WDFN8_0D5_1D0_2D0X2D0
U97 = QFN28-1_0D4_2D4X2D4_4X4
U104-U107 = DFN3X2-14L
U721 = QFN20_3X3_D4
U722 = QFN4X4-24-0-5
U1901 = QFN-32_4X4_0D4
Y1 = CRYSTAL-2P_3D2X1D5_0D9
Y2 Y3 Y10 = CRYSTAL-4P_3D2X2D5_0D9

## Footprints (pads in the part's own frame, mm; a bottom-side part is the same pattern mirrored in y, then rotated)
BGA874_CNP_H_5_MA_KOZ
  round 0.305 smd: A2(-11.46,11.314) A3(-10.959,11.314) A4(-10.459,11.314) A46(10.459,11.314) A47(10.959,11.314) A48(11.46,11.314) AA19(-3.099,1.549) AA20(-2.324,1.549) AA22(-1.549,1.549) AA23(-0.775,1.549) AA25(0,1.549) AA27(0.775,1.549) AA28(1.549,1.549) AA30(2.324,1.549) AA31(3.099,1.549) AB19(-3.099,0.775) AB20(-2.324,0.775) AB22(-1.549,0.775) AB23(-0.775,0.775) AB25(0,0.775) AB27(0.775,0.775) AB28(1.549,0.775) AB30(2.324,0.775) AB31(3.099,0.775) AC6(-9.374,0.579) AC7(-8.612,0.579) AC9(-7.85,0.579) AC11(-7.088,0.579) AC12(-6.326,0.579) AC14(-5.564,0.579) AC15(-4.802,0.579) AC17(-4.04,0.579) AC33(4.04,0.579) AC35(4.802,0.579) AC36(5.564,0.579) AC38(6.326,0.579) AC39(7.088,0.579) AC41(7.85,0.579) AC43(8.612,0.579) AC44(9.374,0.579) AD19(-3.099,0) AD20(-2.324,0) AD22(-1.549,0) AD23(-0.775,0) AD25(0,0) AD27(0.775,0) AD28(1.549,0) AD30(2.324,0) AD31(3.099,0) AE6(-9.374,-0.579) AE7(-8.612,-0.579) AE9(-7.85,-0.579) AE11(-7.088,-0.579) AE12(-6.326,-0.579) AE14(-5.564,-0.579) AE15(-4.802,-0.579) AE17(-4.04,-0.579) AE33(4.04,-0.579) AE35(4.802,-0.579) AE36(5.564,-0.579) AE38(6.326,-0.579) AE39(7.088,-0.579) AE41(7.85,-0.579) AE43(8.612,-0.579) AE44(9.374,-0.579) AF19(-3.099,-0.775) AF20(-2.324,-0.775) AF22(-1.549,-0.775) AF23(-0.775,-0.775) AF25(0,-0.775) AF27(0.775,-0.775) AF28(1.549,-0.775) AF30(2.324,-0.775) AF31(3.099,-0.775) AG19(-3.099,-1.549) AG20(-2.324,-1.549) AG22(-1.549,-1.549) AG23(-0.775,-1.549) AG25(0,-1.549) AG27(0.775,-1.549) AG28(1.549,-1.549) AG30(2.324,-1.549) AG31(3.099,-1.549) AH9(-7.919,-2.205) AH10(-7.18,-2.014) AH12(-6.402,-2.014) AH14(-5.564,-2.014) AH15(-4.789,-2.014) AH17(-4.027,-2.014) AH33(4.027,-2.014) AH35(4.789,-2.014) AH36(5.564,-2.014) AH38(6.402,-2.014) AH40(7.18,-2.014) AH41(7.919,-2.205) AJ6(-9.397,-2.586) AJ7(-8.658,-2.395) AJ19(-3.099,-2.324) AJ20(-2.324,-2.324) AJ22(-1.549,-2.324) AJ23(-0.775,-2.324) AJ25(0,-2.324) AJ27(0.775,-2.324) AJ28(1.549,-2.324) AJ30(2.324,-2.324) AJ31(3.099,-2.324) AJ43(8.658,-2.395) AJ44(9.397,-2.586) AK19(-3.099,-3.099) AK20(-2.324,-3.099) AK22(-1.549,-3.099) AK23(-0.775,-3.099) AK25(0,-3.099) AK27(0.775,-3.099) AK28(1.549,-3.099) AK30(2.324,-3.099) AK31(3.099,-3.099) AL9(-7.914,-3.495) AL10(-7.181,-3.259) AL12(-6.419,-3.259) AL13(-5.657,-3.259) AL15(-4.895,-3.259) AL17(-4.133,-3.259) AL21(-2.014,-3.578) AL24(-0.579,-3.591) AL26(0.579,-3.591) AL29(2.014,-3.578) AL33(4.133,-3.259) AL35(4.895,-3.259) AL37(5.657,-3.259) AL38(6.419,-3.259) AL40(7.181,-3.259) AL41(7.914,-3.495) AM7(-8.635,-3.843) AM18(-3.259,-3.683) AM32(3.259,-3.683) AM43(8.635,-3.843) AN6(-9.295,-4.224) AN10(-7.181,-4.656) AN12(-6.444,-4.351) AN13(-5.682,-4.351) AN15(-4.92,-4.351) AN16(-4.351,-4.394) AN18(-3.259,-4.394) AN21(-2.014,-4.289) AN24(-0.579,-4.302) AN26(0.579,-4.302) AN29(2.014,-4.289) AN32(3.259,-4.394) AN34(4.351,-4.394) AN35(4.92,-4.351) AN37(5.682,-4.351) AN38(6.444,-4.351) AN40(7.181,-4.656) AN44(9.295,-4.224) AP9(-7.914,-4.968) AP21(-2.014,-5.064) AP24(-0.579,-5.064) AP26(0.579,-5.064) AP29(2.014,-5.064) AP41(7.914,-4.968) AR8(-8.508,-5.469) AR12(-6.444,-5.443) AR13(-5.682,-5.443) AR15(-4.92,-5.443) AR16(-4.351,-5.182) AR18(-3.259,-5.156) AR32(3.259,-5.156) AR34(4.351,-5.182) AR35(4.92,-5.443) AR37(5.682,-5.443) AR38(6.444,-5.443) AR42(8.508,-5.469) AT6(-9.295,-5.659) AT10(-7.181,-5.773) AT16(-4.351,-5.944) AT18(-3.259,-5.918) AT21(-2.014,-5.902) AT24(-0.579,-5.826) AT26(0.579,-5.826) AT29(2.014,-5.902) AT32(3.259,-5.918) AT34(4.351,-5.944) AT40(7.181,-5.773) AT44(9.295,-5.659) AU9(-7.914,-6.416) AU24(-0.579,-6.588) AU26(0.579,-6.588) AU41(7.914,-6.416) AV6(-9.295,-7.094) AV7(-8.597,-6.764) AV11(-7.079,-6.975) AV13(-5.748,-6.757) AV16(-4.656,-6.719) AV18(-3.259,-6.68) AV21(-2.014,-6.679) AV29(2.014,-6.679) AV32(3.259,-6.68) AV34(4.656,-6.719) AV37(5.748,-6.757) AV39(7.079,-6.975) AV43(8.597,-6.764) AV44(9.295,-7.094) AW9(-7.824,-7.577) AW10(-7.262,-7.509) AW13(-6.01,-7.49) AW15(-4.892,-7.452) AW18(-3.495,-7.413) AW21(-2.205,-7.419) AW24(-0.579,-7.35) AW26(0.579,-7.35) AW29(2.205,-7.419) AW32(3.495,-7.413) AW35(4.892,-7.452) AW37(6.01,-7.49) AW40(7.262,-7.509) AW41(7.824,-7.577) AY8(-8.533,-7.898) AY42(8.533,-7.898) B1(-11.814,10.96) B2(-11.33,10.83) B3(-10.709,10.878) B47(10.709,10.878) B48(11.33,10.83) B49(11.814,10.96) BA6(-9.13,-8.203) BA12(-6.485,-8.135) BA14(-5.24,-8.135) BA17(-3.843,-8.135) BA20(-2.395,-8.158) BA24(-0.579,-8.112) BA26(0.579,-8.112) BA30(2.395,-8.158) BA33(3.843,-8.135) BA36(5.24,-8.135) BA38(6.485,-8.135) BA44(9.13,-8.203) BB6(-9.088,-8.706) BB7(-8.589,-9) BB9(-8.024,-8.774) BB11(-6.866,-8.795) BB14(-5.621,-8.795) BB16(-4.224,-8.795) BB20(-2.586,-8.897) BB24(-0.579,-8.874) BB26(0.579,-8.874) BB30(2.586,-8.897) BB34(4.224,-8.795) BB36(5.621,-8.795) BB39(6.866,-8.795) BB41(8.024,-8.774) BB43(8.589,-9) BB44(9.088,-8.706) BC5(-9.634,-9.254) BC45(9.634,-9.254) BD1(-11.814,-9.959) BD4(-10.474,-9.983) BD46(10.474,-9.983) BD49(11.814,-9.959) BE1(-11.814,-10.459) BE2(-11.373,-10.196) BE3(-10.86,-10.311) BE4(-10.391,-10.487) BE5(-9.965,-10.212) BE45(9.965,-10.212) BE46(10.391,-10.487) BE47(10.86,-10.311) BE48(11.373,-10.196) BE49(11.814,-10.459) BF1(-11.814,-10.96) BF2(-11.33,-10.83) BF3(-10.709,-10.878) BF47(10.709,-10.878) BF48(11.33,-10.83) BF49(11.814,-10.96) BG2(-11.46,-11.314) BG3(-10.959,-11.314) BG4(-10.459,-11.314) BG46(10.459,-11.314) BG47(10.959,-11.314) BG48(11.46,-11.314) C1(-11.814,10.459) C2(-11.373,10.196) C3(-10.86,10.311) C4(-10.391,10.487) C5(-9.965,10.212) C45(9.965,10.212) C46(10.391,10.487) C47(10.86,10.311) C48(11.373,10.196) C49(11.814,10.459) D1(-11.814,9.959) D4(-10.474,9.983) D46(10.474,9.983) D49(11.814,9.959) E5(-9.634,9.254) E45(9.634,9.254) F6(-9.088,8.706) F7(-8.589,9) F9(-8.024,8.774) F11(-6.866,8.795) F14(-5.621,8.795) F16(-4.224,8.795) F20(-2.586,8.897) F24(-0.579,8.874) F26(0.579,8.874) F30(2.586,8.897) F34(4.224,8.795) F36(5.621,8.795) F39(6.866,8.795) F41(8.024,8.774) F43(8.589,9) F44(9.088,8.706) G6(-9.13,8.203) G12(-6.485,8.135) G14(-5.24,8.135) G17(-3.843,8.135) G20(-2.395,8.158) G24(-0.579,8.112) G26(0.579,8.112) G30(2.395,8.158) G33(3.843,8.135) G36(5.24,8.135) G38(6.485,8.135) G44(9.13,8.203) H8(-8.533,7.898) H42(8.533,7.898) J9(-7.824,7.577) J10(-7.262,7.509) J13(-6.01,7.49) J15(-4.892,7.452) J18(-3.495,7.413) J21(-2.205,7.419) J24(-0.579,7.35) J26(0.579,7.35) J29(2.205,7.419) J32(3.495,7.413) J35(4.892,7.452) J37(6.01,7.49) J40(7.262,7.509) J41(7.824,7.577) K6(-9.295,7.094) K7(-8.597,6.764) K11(-7.079,6.975) K13(-5.748,6.757) K16(-4.656,6.719) K18(-3.259,6.68) K21(-2.014,6.679) K29(2.014,6.679) K32(3.259,6.68) K34(4.656,6.719) K37(5.748,6.757) K39(7.079,6.975) K43(8.597,6.764) K44(9.295,7.094) L9(-7.914,6.416) L24(-0.579,6.588) L26(0.579,6.588) L41(7.914,6.416) M6(-9.295,5.659) M10(-7.181,5.773) M16(-4.351,5.944) M18(-3.259,5.918) M21(-2.014,5.902) M24(-0.579,5.826) M26(0.579,5.826) M29(2.014,5.902) M32(3.259,5.918) M34(4.351,5.944) M40(7.181,5.773) M44(9.295,5.659) N8(-8.508,5.469) N12(-6.444,5.443) N13(-5.682,5.443) N15(-4.92,5.443) N16(-4.351,5.182) N18(-3.259,5.156) N32(3.259,5.156) N34(4.351,5.182) N35(4.92,5.443) N37(5.682,5.443) N38(6.444,5.443) N42(8.508,5.469) P9(-7.914,4.968) P21(-2.014,5.064) P24(-0.579,5.064) P26(0.579,5.064) P29(2.014,5.064) P41(7.914,4.968) R6(-9.295,4.224) R10(-7.181,4.656) R12(-6.444,4.351) R13(-5.682,4.351) R15(-4.92,4.351) R16(-4.351,4.394) R18(-3.259,4.394) R21(-2.014,4.289) R24(-0.579,4.302) R26(0.579,4.302) R29(2.014,4.289) R32(3.259,4.394) R34(4.351,4.394) R35(4.92,4.351) R37(5.682,4.351) R38(6.444,4.351) R40(7.181,4.656) R44(9.295,4.224) T7(-8.635,3.843) T17(-3.811,3.683) T18(-3.259,3.683) T32(3.259,3.683) T43(8.635,3.843) U9(-7.914,3.495) U10(-7.181,3.259) U12(-6.419,3.259) U13(-5.657,3.259) U15(-4.895,3.259) U17(-4.133,3.259) U21(-2.014,3.578) U24(-0.579,3.591) U26(0.579,3.591) U29(2.014,3.578) U33(4.133,3.259) U35(4.895,3.259) U37(5.657,3.259) U38(6.419,3.259) U40(7.181,3.259) U41(7.914,3.495) V19(-3.099,3.099) V20(-2.324,3.099) V22(-1.549,3.099) V23(-0.775,3.099) V25(0,3.099) V27(0.775,3.099) V28(1.549,3.099) V30(2.324,3.099) V31(3.099,3.099) W6(-9.397,2.586) W7(-8.658,2.395) W19(-3.099,2.324) W20(-2.324,2.324) W22(-1.549,2.324) W23(-0.775,2.324) W25(0,2.324) W27(0.775,2.324) W28(1.549,2.324) W30(2.324,2.324) W31(3.099,2.324) W43(8.658,2.395) W44(9.397,2.586) Y9(-7.919,2.205) Y10(-7.18,2.014) Y12(-6.402,2.014) Y14(-5.564,2.014) Y15(-4.789,2.014) Y17(-4.027,2.014) Y33(4.027,2.014) Y35(4.789,2.014) Y36(5.564,2.014) Y38(6.402,2.014) Y40(7.18,2.014) Y41(7.919,2.205)
  round 0.279 smd: A5(-9.958,11.314) A45(9.958,11.314) BC1(-11.814,-9.458) BC49(11.814,-9.458) BG5(-9.958,-11.314) BG45(9.958,-11.314) E1(-11.814,9.458) E49(11.814,9.458)
  oval 0.203x0.254 smd: A6(-9.399,11.314) A8(-8.294,11.314) A42(8.294,11.314) A44(9.399,11.314) BD8(-8.411,-9.813) BD12(-6.214,-9.813) BD17(-4.017,-9.813) BD21(-1.82,-9.813) BD29(1.82,-9.813) BD33(4.017,-9.813) BD38(6.214,-9.813) BD42(8.411,-9.813) BE9(-7.784,-10.186) BE10(-7.283,-10.059) BE14(-5.587,-10.186) BE15(-5.086,-10.059) BE18(-3.39,-10.186) BE19(-2.889,-10.059) BE23(-1.193,-10.186) BE24(-0.692,-10.059) BE26(0.692,-10.059) BE27(1.193,-10.186) BE31(2.889,-10.059) BE32(3.39,-10.186) BE35(5.086,-10.059) BE36(5.587,-10.186) BE40(7.283,-10.059) BE41(7.784,-10.186) BG6(-9.399,-11.314) BG8(-8.294,-11.314) BG42(8.294,-11.314) BG44(9.399,-11.314) C9(-7.784,10.186) C10(-7.283,10.059) C14(-5.587,10.186) C15(-5.086,10.059) C18(-3.39,10.186) C19(-2.889,10.059) C23(-1.193,10.186) C24(-0.692,10.059) C26(0.692,10.059) C27(1.193,10.186) C31(2.889,10.059) C32(3.39,10.186) C35(5.086,10.059) C36(5.587,10.186) C40(7.283,10.059) C41(7.784,10.186) D8(-8.411,9.813) D12(-6.214,9.813) D17(-4.017,9.813) D21(-1.82,9.813) D29(1.82,9.813) D33(4.017,9.813) D38(6.214,9.813) D42(8.411,9.813)
  oval 0.152x0.254 smd: A13(-6.072,11.314) A17(-3.875,11.314) A22(-1.678,11.314) A25(0,11.314) A28(1.678,11.314) A33(3.875,11.314) A37(6.072,11.314) B10(-7.123,10.603) B12(-6.265,10.816) B14(-5.587,10.687) B15(-4.926,10.603) B17(-4.068,10.816) B18(-3.39,10.687) B19(-2.729,10.603) B21(-1.871,10.816) B23(-1.193,10.687) B24(-0.532,10.603) B25(0,10.806) B26(0.532,10.603) B27(1.193,10.687) B29(1.871,10.816) B31(2.729,10.603) B32(3.39,10.687) B33(4.068,10.816) B35(4.926,10.603) B36(5.587,10.687) B38(6.265,10.816) B40(7.123,10.603) BE11(-6.76,-10.118) BE12(-6.295,-10.313) BE16(-4.563,-10.118) BE17(-4.098,-10.313) BE20(-2.366,-10.118) BE21(-1.901,-10.313) BE25(0,-10.298) BE29(1.901,-10.313) BE30(2.366,-10.118) BE33(4.098,-10.313) BE34(4.563,-10.118) BE38(6.295,-10.313) BE39(6.76,-10.118) BF10(-7.123,-10.603) BF12(-6.265,-10.816) BF14(-5.587,-10.687) BF15(-4.926,-10.603) BF17(-4.068,-10.816) BF18(-3.39,-10.687) BF19(-2.729,-10.603) BF21(-1.871,-10.816) BF23(-1.193,-10.687) BF24(-0.532,-10.603) BF25(0,-10.806) BF26(0.532,-10.603) BF27(1.193,-10.687) BF29(1.871,-10.816) BF31(2.729,-10.603) BF32(3.39,-10.687) BF33(4.068,-10.816) BF35(4.926,-10.603) BF36(5.587,-10.687) BF38(6.265,-10.816) BF40(7.123,-10.603) BG13(-6.072,-11.314) BG17(-3.875,-11.314) BG22(-1.678,-11.314) BG25(0,-11.314) BG28(1.678,-11.314) BG33(3.875,-11.314) BG37(6.072,-11.314) C11(-6.76,10.118) C12(-6.295,10.313) C16(-4.563,10.118) C17(-4.098,10.313) C20(-2.366,10.118) C21(-1.901,10.313) C25(0,10.298) C29(1.901,10.313) C30(2.366,10.118) C33(4.098,10.313) C34(4.563,10.118) C38(6.295,10.313) C39(6.76,10.118)
  oval 0.254x0.152 smd: AA1(-11.814,1.678) AA49(11.814,1.678) AB2(-11.187,1.193) AB48(11.187,1.193) AC2(-11.103,0.532) AC48(11.103,0.532) AD1(-11.814,0) AD2(-11.306,0) AD3(-10.798,0) AD47(10.798,0) AD48(11.306,0) AD49(11.814,0) AE2(-11.103,-0.532) AE48(11.103,-0.532) AF2(-11.187,-1.193) AF48(11.187,-1.193) AG1(-11.814,-1.678) AG49(11.814,-1.678) AH2(-11.316,-1.871) AH3(-10.813,-1.901) AH47(10.813,-1.901) AH48(11.316,-1.871) AJ3(-10.618,-2.366) AJ47(10.618,-2.366) AK2(-11.103,-2.729) AK48(11.103,-2.729) AL2(-11.187,-3.39) AL48(11.187,-3.39) AM1(-11.814,-3.875) AM2(-11.316,-4.068) AM3(-10.813,-4.098) AM47(10.813,-4.098) AM48(11.316,-4.068) AM49(11.814,-3.875) AN3(-10.618,-4.563) AN47(10.618,-4.563) AP2(-11.103,-4.926) AP48(11.103,-4.926) P2(-11.103,4.926) P48(11.103,4.926) R3(-10.618,4.563) R47(10.618,4.563) T1(-11.814,3.875) T2(-11.316,4.068) T3(-10.813,4.098) T47(10.813,4.098) T48(11.316,4.068) T49(11.814,3.875) U2(-11.187,3.39) U48(11.187,3.39) V2(-11.103,2.729) V48(11.103,2.729) W3(-10.618,2.366) W47(10.618,2.366) Y2(-11.316,1.871) Y3(-10.813,1.901) Y47(10.813,1.901) Y48(11.316,1.871)
  round 0.254 smd: AA5(-9.856,1.601) AA45(9.856,1.601) AC4(-10.06,0.579) AC46(10.06,0.579) AE4(-10.06,-0.579) AE46(10.06,-0.579) AG5(-9.856,-1.601) AG45(9.856,-1.601) AJ4(-10.098,-2.274) AJ46(10.098,-2.274) AK4(-10.06,-2.776) AK46(10.06,-2.776) AM5(-9.856,-3.799) AM45(9.856,-3.799) AN4(-10.098,-4.471) AN46(10.098,-4.471) AP4(-10.06,-4.973) AP46(10.06,-4.973) AT5(-9.856,-5.996) AT45(9.856,-5.996) AV4(-10.098,-6.669) AV46(10.098,-6.669) AW4(-10.06,-7.17) AW46(10.06,-7.17) B6(-9.397,10.811) B44(9.397,10.811) BA2(-11.316,-8.526) BA3(-10.809,-8.594) BA4(-10.304,-8.468) BA5(-9.856,-8.193) BA45(9.856,-8.193) BA46(10.304,-8.468) BA47(10.809,-8.594) BA48(11.316,-8.526) BB3(-11.318,-9.315) BB4(-10.825,-9.126) BB46(10.825,-9.126) BB47(11.318,-9.315) BC8(-8.193,-9.356) BC10(-7.17,-9.56) BC13(-5.996,-9.356) BC15(-4.973,-9.56) BC17(-3.799,-9.356) BC19(-2.776,-9.56) BC22(-1.601,-9.356) BC24(-0.579,-9.56) BC26(0.579,-9.56) BC28(1.601,-9.356) BC31(2.776,-9.56) BC33(3.799,-9.356) BC35(4.973,-9.56) BC37(5.996,-9.356) BC40(7.17,-9.56) BC42(8.193,-9.356) BD7(-8.914,-9.872) BD11(-6.669,-9.598) BD16(-4.471,-9.598) BD20(-2.274,-9.598) BD30(2.274,-9.598) BD34(4.471,-9.598) BD39(6.669,-9.598) BD43(8.914,-9.872) BE6(-9.091,-10.357) BE44(9.091,-10.357) BF6(-9.397,-10.811) BF44(9.397,-10.811) C6(-9.091,10.357) C44(9.091,10.357) D7(-8.914,9.872) D11(-6.669,9.598) D16(-4.471,9.598) D20(-2.274,9.598) D30(2.274,9.598) D34(4.471,9.598) D39(6.669,9.598) D43(8.914,9.872) E8(-8.193,9.356) E10(-7.17,9.56) E13(-5.996,9.356) E15(-4.973,9.56) E17(-3.799,9.356) E19(-2.776,9.56) E22(-1.601,9.356) E24(-0.579,9.56) E26(0.579,9.56) E28(1.601,9.356) E31(2.776,9.56) E33(3.799,9.356) E35(4.973,9.56) E37(5.996,9.356) E40(7.17,9.56) E42(8.193,9.356) F3(-11.318,9.315) F4(-10.825,9.126) F46(10.825,9.126) F47(11.318,9.315) G2(-11.316,8.526) G3(-10.809,8.594) G4(-10.304,8.468) G5(-9.856,8.193) G45(9.856,8.193) G46(10.304,8.468) G47(10.809,8.594) G48(11.316,8.526) J4(-10.06,7.17) J46(10.06,7.17) K4(-10.098,6.669) K46(10.098,6.669) M5(-9.856,5.996) M45(9.856,5.996) P4(-10.06,4.973) P46(10.06,4.973) R4(-10.098,4.471) R46(10.098,4.471) T5(-9.856,3.799) T45(9.856,3.799) V4(-10.06,2.776) V46(10.06,2.776) W4(-10.098,2.274) W46(10.098,2.274)
  oval 0.254x0.203 smd: AB3(-10.686,1.193) AB47(10.686,1.193) AC3(-10.559,0.692) AC47(10.559,0.692) AE3(-10.559,-0.692) AE47(10.559,-0.692) AF3(-10.686,-1.193) AF47(10.686,-1.193) AH4(-10.313,-1.82) AH46(10.313,-1.82) AK3(-10.559,-2.883) AK47(10.559,-2.883) AL3(-10.686,-3.39) AL47(10.686,-3.39) AM4(-10.313,-4.017) AM46(10.313,-4.017) AP3(-10.559,-5.08) AP47(10.559,-5.08) AR3(-10.686,-5.587) AR47(10.686,-5.587) AT1(-11.814,-6.097) AT49(11.814,-6.097) AU4(-10.313,-6.214) AU46(10.313,-6.214) AW3(-10.559,-7.277) AW47(10.559,-7.277) AY3(-10.686,-7.784) AY47(10.686,-7.784) BA1(-11.814,-8.32) BA49(11.814,-8.32) G1(-11.814,8.32) G49(11.814,8.32) H3(-10.686,7.784) H47(10.686,7.784) J3(-10.559,7.277) J47(10.559,7.277) L4(-10.313,6.214) L46(10.313,6.214) M1(-11.814,6.097) M49(11.814,6.097) N3(-10.686,5.587) N47(10.686,5.587) P3(-10.559,5.08) P47(10.559,5.08) T4(-10.313,4.017) T46(10.313,4.017) U3(-10.686,3.39) U47(10.686,3.39) V3(-10.559,2.883) V47(10.559,2.883) Y4(-10.313,1.82) Y46(10.313,1.82)
  oval 0.305x0.152 smd: AR2(-11.187,-5.587) AR48(11.187,-5.587) AU2(-11.316,-6.265) AU3(-10.813,-6.295) AU47(10.813,-6.295) AU48(11.316,-6.265) AV3(-10.618,-6.76) AV47(10.618,-6.76) AW2(-11.103,-7.123) AW48(11.103,-7.123) AY2(-11.187,-7.784) AY48(11.187,-7.784) H2(-11.187,7.784) H48(11.187,7.784) J2(-11.103,7.123) J48(11.103,7.123) K3(-10.618,6.76) K47(10.618,6.76) L2(-11.316,6.265) L3(-10.813,6.295) L47(10.813,6.295) L48(11.316,6.265) N2(-11.187,5.587) N48(11.187,5.587)
  oval 0.152x0.305 smd: B8(-8.462,10.816) B9(-7.784,10.687) B41(7.784,10.687) B42(8.462,10.816) BE8(-8.492,-10.313) BE42(8.492,-10.313) BF8(-8.462,-10.816) BF9(-7.784,-10.687) BF41(7.784,-10.687) BF42(8.462,-10.816) C8(-8.492,10.313) C42(8.492,10.313)
